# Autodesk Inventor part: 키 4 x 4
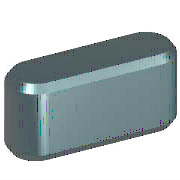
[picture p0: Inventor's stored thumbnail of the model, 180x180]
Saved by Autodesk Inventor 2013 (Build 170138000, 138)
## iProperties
IsCustomPart: 1
Created: 2012-02
Part Number: 키 4 x 4
Material: 강철, 연강
Description: 키 및 해당 키홈
Document SubType Name: Modeling
Standard: KS B 1311
Designer: mduedu
Standards Organization: KS
Language: ko-KR
Size Designation: 4 x 4 x 18
Categories: <MemberInstance><Categories><Category DisplayName="샤프트 부품" InternalName="7f7aeb1f-a693-4053-b835-cee3144e0d98" Mnemonic="SHFT"><Category DisplayName="키" Interna
Density: 7.86 g/cm^3
Mass: 2.13606 g
Surface Area: 2.87354 cm^2
Volume: 0.271763 cm^3
Author: mduedu
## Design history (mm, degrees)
workplane "Work Plane1"
workplane "Work Plane2"
sketch "스케치1"
  geometry: L1 (2, 2)-(16, 2); L2 (16, -2)-(2, -2); L3 (0, 9.4)-(0, -7.4) reference; L4 (-5, 0)-(30, 0) reference; L5 (18, 0)-(18, 7); A1 r 2 centre (2, 0) between (2, 2) and (2, -2); A2 r 2 centre (16, 0) between (16, -2) and (16, 2)
  constraints: 6 end point, 5 point on circle, 4 tangent, 3 point on line, 2 centre point, 1 horizontal, 1 parallel, 1 perpendicular
  dimensions: "d0" = 2 radius of A1 (= 0.5 x PB); "d13" = 2 radius of A2 (= 0.5 x PB); "d14" = 18 distance between parallel lines of L5 L3 (= NLG)
extrude "본체1" new body sketch "스케치1" taper "d3" = 0 deg; stored distance "d4" = 10
workplane "Work Plane3"
body "Solid1"
chamfer "모따기1" distance "d8" = 0.25 (= PHH); stored, may be unused: second distance "d9" = 0.25 (= PHH), angle "d15" = 45 deg
other parameters: "d1" = -2.5 (= -PNT), "d2" = 1.5 (= PH - PNT), "NLG" = 18 [user parameter; used in 3 equation terms], "PB" = 4 [user parameter; used in 2 equation terms], "PNT" = 2.5 [user parameter; used in 2 equation terms], "PH" = 4 [user parameter; used in 1 equation term], "PHH" = 0.25 [user parameter; used in 2 equation terms], "d10" = 0, "d16" = 0, "d17" = 0, "d18" = 0, "PLB2" = 18 (= NLG) [user parameter], "WDMAX" = 12 [user parameter], "PLB1" = 18 (= NLG) [user parameter], "RR" = 0.08 [user parameter], "PUEB" = 1.8 [user parameter]
